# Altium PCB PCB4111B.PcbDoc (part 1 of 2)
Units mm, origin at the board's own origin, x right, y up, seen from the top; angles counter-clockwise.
Board outline 30 x 47 mm, 4 copper layers (Top Layer, Signal Layer 2, Signal Layer 3, Bottom Layer), stack 1.556 mm thick; 81 components, 93 nets, 294 pads, 415 vias.
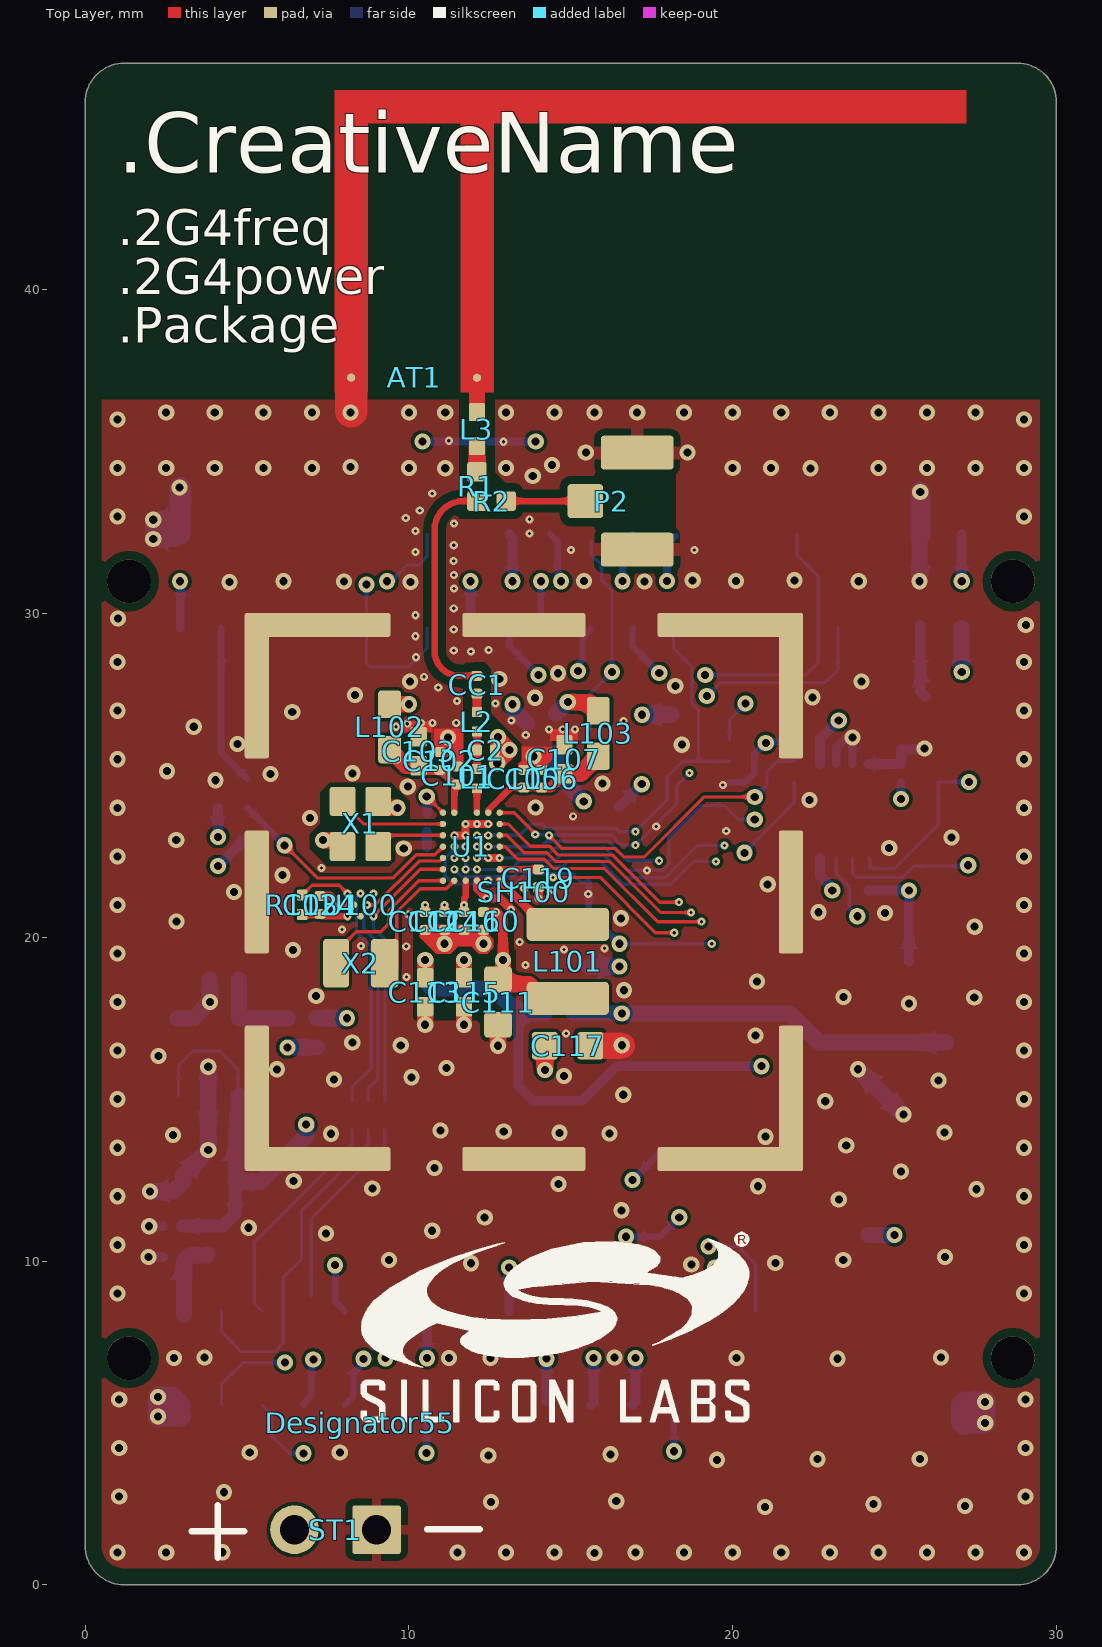
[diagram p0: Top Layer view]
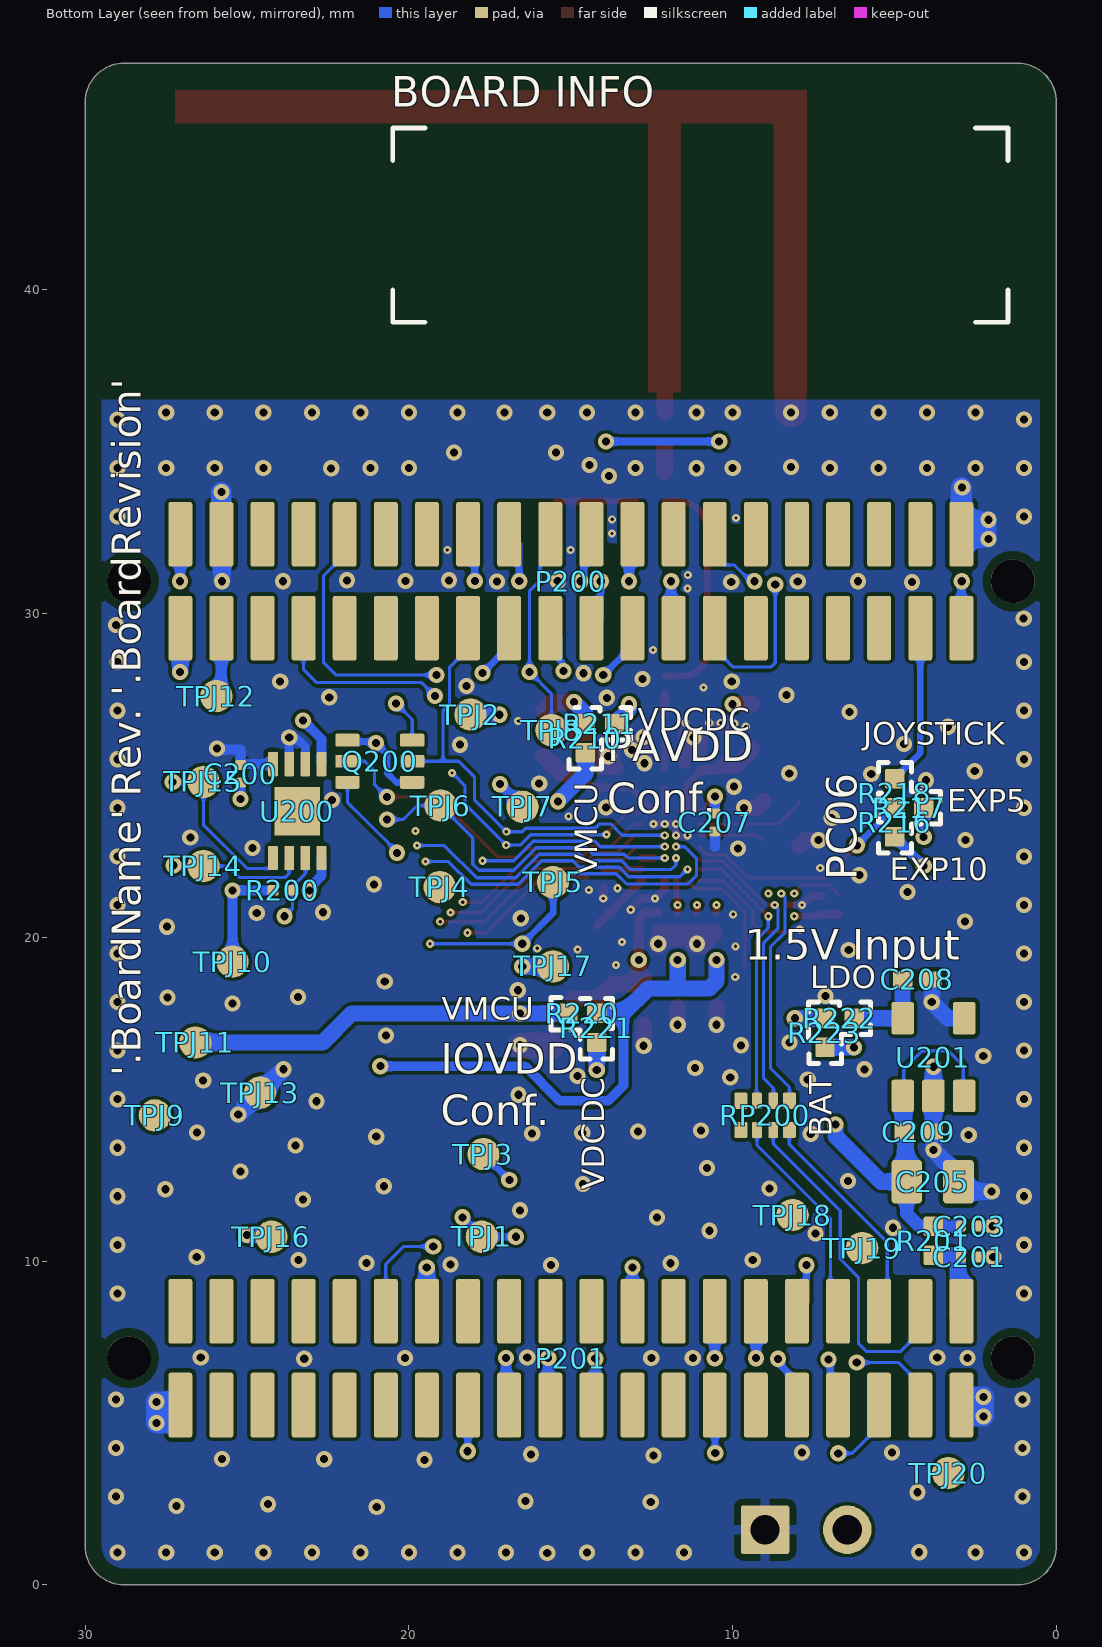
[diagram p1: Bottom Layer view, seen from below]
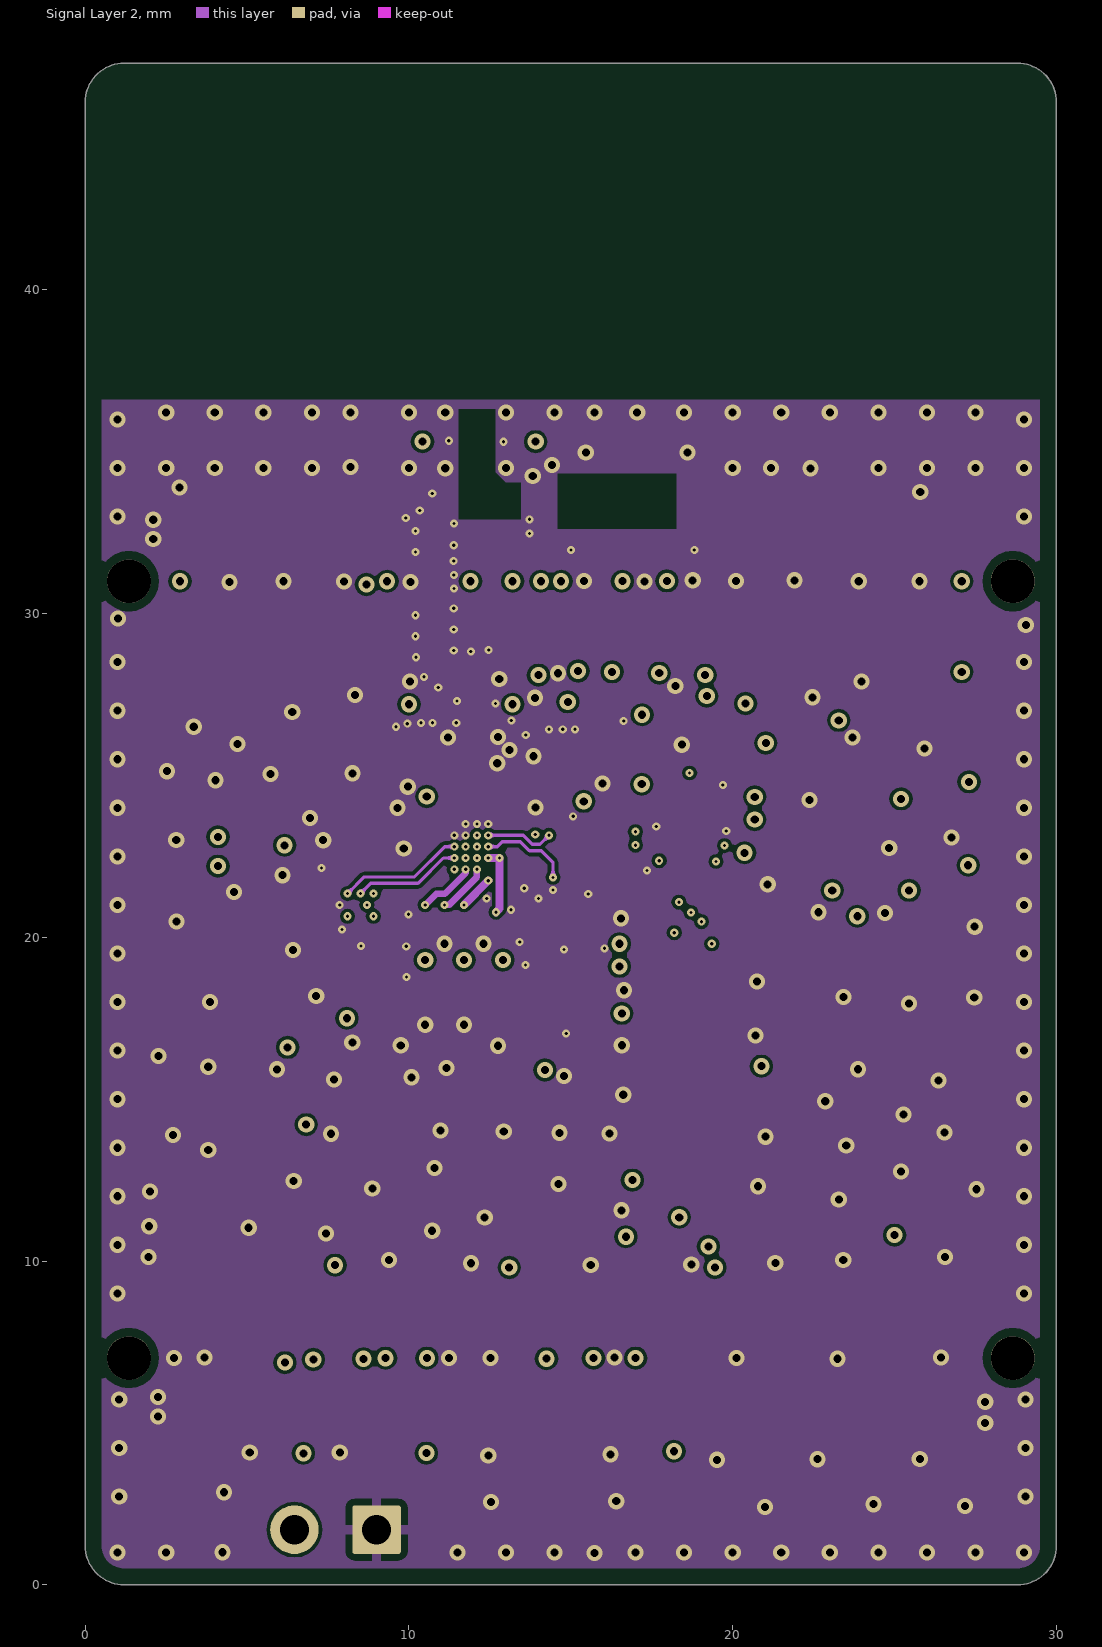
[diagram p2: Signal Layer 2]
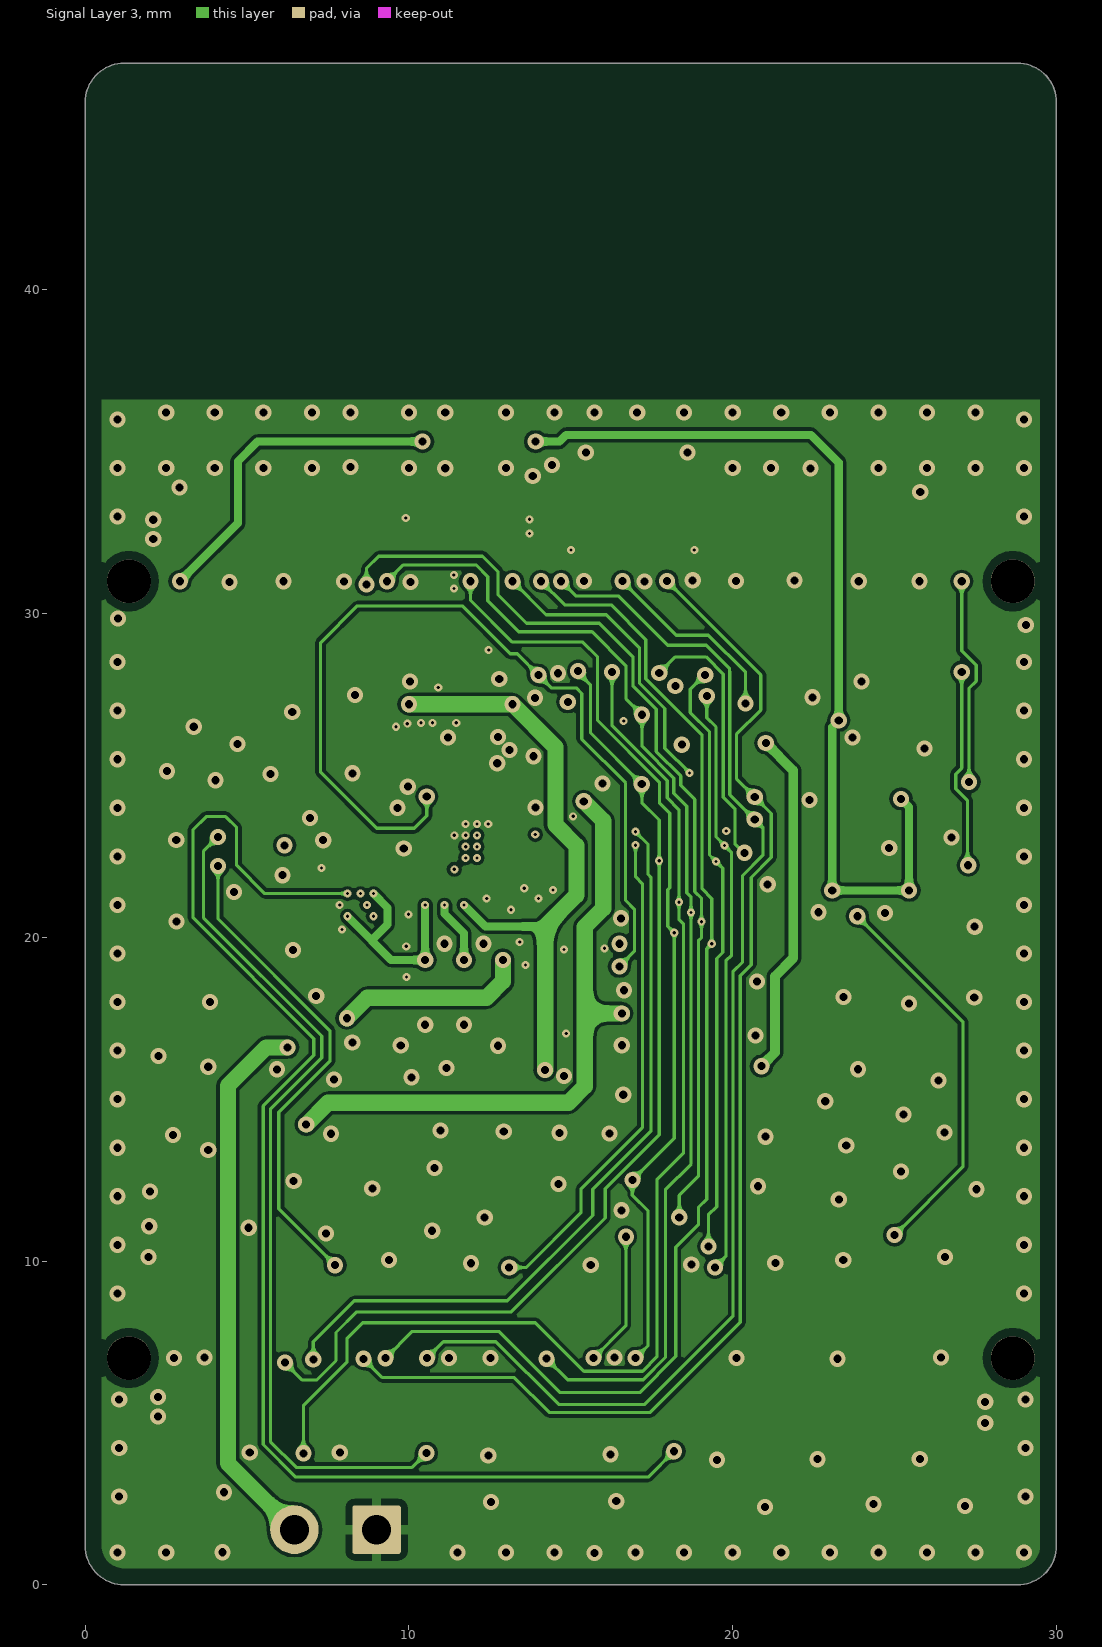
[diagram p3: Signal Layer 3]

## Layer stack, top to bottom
Top Solder: solder mask 0.0102, Solder Resist, Dk 3.5
Top Layer: signal copper 0.035
Dielectric 1: core 0.1, FR-4, Dk 4.2
Signal Layer 2: signal copper 0.018
Dielectric 3: prepreg 1.25, Dk 4.2
Signal Layer 3: signal copper 0.018
Dielectric 2: core 0.1, Dk 4.2
Bottom Layer: signal copper 0.035
Bottom Solder: solder mask 0.0102, Solder Resist, Dk 3.5

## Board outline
0,1.2 ccw(c1.2,1.2) 1.2,0 28.8,0 ccw(c28.8,1.2) 30,1.2 30,45.8 ccw(c28.8,45.8) 28.8,47 1.2,47 ccw(c1.2,45.8) 0,45.8

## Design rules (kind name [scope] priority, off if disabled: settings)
AcuteAngle [All] p1: minimum=7.00000000000000E+0001 checktracksonly=FALSE
BoardOutlineClearance [All] p1: gap=0.5 ignorepadtopadclearanceinfootprint=FALSE
Clearance Clearance_50Ohm [InNet('50R*') vs InNet('GND')] p1: gap=0.254 ignorepadtopadclearanceinfootprint=FALSE except(0: Arc-Hole Track-Hole SMDPad-Hole THPad-Hole Via-Hole Fill-Hole Poly-Hole Region-Hole Text-Hole)
Clearance Clearance_to_Holes [InPadClass('NPTH')] p2: gap=0.254 ignorepadtopadclearanceinfootprint=FALSE except(0: Arc-Hole Track-Hole SMDPad-Hole THPad-Hole Via-Hole Fill-Hole Poly-Hole Region-Hole Text-Hole)
Clearance Clerance_Polygon [InPolygon] p3: gap=0.1 ignorepadtopadclearanceinfootprint=FALSE except(0: Arc-Hole Track-Hole SMDPad-Hole THPad-Hole Via-Hole Fill-Hole Poly-Hole Region-Hole Text-Hole)
Clearance Clearance_General [All] p4: gap=0.1 ignorepadtopadclearanceinfootprint=FALSE except(0: Arc-Hole Track-Hole SMDPad-Hole THPad-Hole Via-Hole Fill-Hole Poly-Hole Region-Hole Text-Hole)
HoleToHoleClearance HoleToHoleClearance_ANT1toPAD [Incomponent ('ANT1') vs ISpad] p1: gap=0 allowstackedmicrovias=TRUE
HoleToHoleClearance HoleToHoleClearance_R1toR2_1 [Incomponent ('R1') vs Incomponent ('R2')] p2: gap=0 allowstackedmicrovias=TRUE
HoleToHoleClearance HoleToHoleClearance_U1toVIA_1 [InComponent ('U1') vs IsVia] p3: gap=0 allowstackedmicrovias=TRUE
HoleToHoleClearance [All] p4: gap=0.245 allowstackedmicrovias=TRUE
MinimumSolderMaskSliver [All] p1: minsoldermaskwidth=0.075
PolygonConnect PolygonConnect_TH [InComponent('ST1') or InComponent('P2')] p1: thpad.connectstyle=Relief thpad.reliefconductorwidth=0.3 thpad.reliefentries=4 thpad.polygonreliefangle="90 Angle" thpad.airgapwidth=0.2 smdpad.connectstyle=Relief smdpad.reliefconductorwidth=0.4 smdpad.reliefentries=4 smdpad.polygonreliefangle="90 Angle" smdpad.airgapwidth=0.2 via.connectstyle=Relief via.reliefconductorwidth=0.254 via.reliefentries=4 via.polygonreliefangle="90 Angle" via.airgapwidth=0.254
PolygonConnect Polygon_VIA_Connect [IsVia] p2: connectstyle=Direct reliefconductorwidth=0.254 reliefentries=4 polygonreliefangle="90 Angle" airgapwidth=0.254
PolygonConnect PolygonConnect_SH100 [InComponent('SH100')] p3: connectstyle=Direct reliefconductorwidth=0.254 reliefentries=4 polygonreliefangle="90 Angle" airgapwidth=0.127
PolygonConnect [All] p4: connectstyle=NoConnect reliefconductorwidth=0.254 reliefentries=4 polygonreliefangle="90 Angle" airgapwidth=0.127
RoutingVias [All] p1: holewidth=0.3 width=0.65 viastyle="Through Hole" minholewidth=0.25 minwidth=0.5 maxholewidth=1 maxwidth=1.5
ShortCircuit ShortCircuit_ANTtoPAD [InNet('NetAT1_1') vs InNet('GND')] p1: allowed=TRUE
ShortCircuit ShortCircuit_R1toR2_1 [Incomponent ('R1') vs Incomponent ('R2')] p2: allowed=TRUE
ShortCircuit [All] p3: allowed=FALSE
SilkToSilkClearance [All] p1: silktosilkclearance=0.102
SilkToSolderMaskClearance [IsPad] p1: minsilkscreentomaskgap=0.102 clearancetoexposedcopper=TRUE
SolderMaskExpansion [All] p1: expansion=0.051 istentingtop=FALSE
Width 50ohm [InNet('50R*')] p1: maxlimit=0.55 minlimit=0.2 preferedwidth=0.2
Width [All] p2: maxlimit=5.08 minlimit=0.1 preferedwidth=0.125
25 further rules are at their usual default settings.

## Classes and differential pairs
pad class NPTH: P200-M1 P200-M2 P201-M1 P201-M2

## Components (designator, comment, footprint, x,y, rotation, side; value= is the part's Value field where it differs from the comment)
AT1 "INVERTED_F" EM358x_INVERTED_F 7.714,36.835 r0 top net-tie
C2 "1P3" C0201_L 12.375,25.78 r0 top
C101 "120P" C0201_L 11.5,25 r90 top
C102 "100N" C0201_L 10.95,25.45 r90 top
C103 "1U" C0402_L#1 10.3,25.75 r90 top
C105 "120P" C0201_L 13.55,24.9 r90 top
C106 "100N" C0201_L 14.1,24.9 r90 top
C107 "1U" C0402_L#1 14.8,25.5 r90 top
C110 "100N" C0201_L 12.3,20.5 r270 top
C111 "10U" C0603_L 12.75,18 r270 top
C112 "10N" C0201_L 10.5,20.5 r270 top
C113 "1U" C0402_L#1 10.5,18.3 r270 top
C114 "100N" C0201_L 11.1,20.5 r270 top
C115 "1U" C0402_L#2 11.7,18.3 r270 top
C116 "100N" C0201_L 11.7,20.5 r270 top
C117 "4U7" C0603_L 14.9,16.65 r0 top
C119 "1U" C0201_L 14,21.825 r270 top
C124 "100N" C0201_L 7.25,21 r90 top
C200 "100N" C0201_L 25.2,25.05 r90 bottom
C201 "100N" C0201_L 2.675,10.125 r180 bottom
C203 "100N" C0201_L 2.675,11.075 r180 bottom
C205 "10U" C0805_L 3.825,12.45 r180 bottom
C207 "100N" C0201_L 10.55,23.55 r270 bottom
C208 "1U" C0402_L#1 4.3,18.7 r180 bottom
C209 "1U" C0402_L#1 4.25,14 r180 bottom
CC1 "18P" C0201_L 12.1,27.8 r90 top
Designator39 "Comment" PCB_SPEC_4_LAYER -68.7,110.2 r0 top
Designator55 "Comment" LOGO_SILABS_W12.0 8.5,5 r0 top
L1 "3N5" COIL_0201_L 12.1,24.9 r90 top
L2 "3N8" COIL_0201_L 12.1,26.66 r90 top
L3 "0R" COIL_0402_L 12.1,35.7 r90 top
L101 "2U2" COIL_1008_L 14.908,19.257 r270 top
L102 "BLM18AG102SN1" COIL_MUR_BLM18_0603 9.4,26.5 r270 top
L103 "BLM18AG102SN1" COIL_MUR_BLM18_0603 15.85,26.3 r270 top
P2 "U.FL" COAX_HIROSE_U.FL_CL331-0471 17.05,33.475 r90 top
P200 "SOCKET_WCON_2X20_1.27MM_SMD" SAM_SFC-120-T2-D-A-2X20_SNUM 15,31 r0 bottom locked
P201 "SOCKET_WCON_2X20_1.27MM_SMD" SAM_SFC-120-T2-D-A-2X20_SNUM 15,7 r0 bottom locked
Q200 "BSS84" SOT-363 20.903,25.439 r0 bottom
R1 "0R" R0402_L 12.1,33.925 r90 top
R2 "0R" R0402_L 12.55,33.475 r0 top
R103 "330K" R0201_L 6.7,21 r270 top
R200 "10K" R0201_L 23.9,21.45 r0 bottom
R201 "0R" R0402_L 3.8,10.625 r90 bottom
R210 "0R" R0402_L 14.55,26.15 r270 bottom
R211 "0R" R0402_L 14.1,26.6 r0 bottom
R216 "0R" R0402_L 5.001,23.55 r270 bottom
R217 "0R" R0402_L 4.55,24 r180 bottom
R218 "0R" R0402_L 5,24.45 r90 bottom
R220 "0R" R0402_L 14.65,17.65 r0 bottom
R221 "0R" R0402_L 14.2,17.2 r90 bottom
R222 "0R" R0402_L 6.7,17.5 r0 bottom
R223 "0R" R0402_L 7.15,17.05 r90 bottom
RP200 "100R" RES_MNR04-8 9,14.5 r0 bottom
SH100 "RF_SHIELD_FRAME_BMI-S-202-F" LAIRD_BMI-S-202-F 13.55,21.4 r90 top locked
ST1 "2X1 2.54MM" HEADER2X1_2.54MM_TH 9,1.7 r180 top
TPJ1 "TPJ_SMD" TP_1.0_SMD 17.75,10.75 r90 bottom locked
TPJ2 "TPJ_SMD" TP_1.0_SMD 18.1,26.88 r90 bottom locked
TPJ3 "TPJ_SMD" TP_1.0_SMD 17.7,13.3 r90 bottom locked
TPJ4 "TPJ_SMD" TP_1.0_SMD 19.05,21.55 r90 bottom locked
TPJ5 "TPJ_SMD" TP_1.0_SMD 15.55,21.7 r90 bottom locked
TPJ6 "TPJ_SMD" TP_1.0_SMD 19.02,24.07 r90 bottom locked
TPJ7 "TPJ_SMD" TP_1.0_SMD 16.49,24.03 r90 bottom locked
TPJ8 "TPJ_SMD" TP_1.0_SMD 15.6,26.4 r90 bottom locked
TPJ9 "TPJ_SMD" TP_1.0_SMD 27.85,14.5 r90 bottom locked
TPJ10 "TPJ_SMD" TP_1.0_SMD 25.45,19.25 r90 bottom locked
TPJ11 "TPJ_SMD" TP_1.0_SMD 26.6,16.75 r90 bottom locked
TPJ12 "TPJ_SMD" TP_1.0_SMD 25.95,27.45 r90 bottom locked
TPJ13 "TPJ_SMD" TP_1.0_SMD 24.6,15.2 r90 bottom locked
TPJ14 "TPJ_SMD" TP_1.0_SMD 26.35,22.2 r90 bottom locked
TPJ15 "TPJ_SMD" TP_1.0_SMD 26.35,24.8 r90 bottom locked
TPJ16 "TPJ_SMD" TP_1.0_SMD 24.25,10.75 r90 bottom locked
TPJ17 "TPJ_SMD" TP_1.0_SMD 15.55,19.1 r90 bottom locked
TPJ18 "TPJ_SMD" TP_1.0_SMD 8.15,11.42 r90 bottom locked
TPJ19 "TPJ_SMD" TP_1.0_SMD 6,10.4 r90 bottom locked
TPJ20 "TPJ_SMD" TP_1.0_SMD 3.34,3.45 r90 bottom locked
U1 "EFR32BG27C320F768GJ39-A" WLCSP39 11.925,22.8 r180 top
U100 "MX25R8035F" BGA8_M040_1.24X1.75_WLCSP 8.5,21 r90 top
U200 "24AA024" TDFN8_M050_2.0X3.0_EP 23.45,23.9 r270 bottom
U201 "TPS7A03" SOT-23-5 3.8,16.3 r90 bottom
X1 "38.4MHz" KDS_DSX211SH_2016 8.5,23.5 r90 top
X2 "32.768 kHz" X_MCS_CM8V-T1A 8.5,19.2 r0 top

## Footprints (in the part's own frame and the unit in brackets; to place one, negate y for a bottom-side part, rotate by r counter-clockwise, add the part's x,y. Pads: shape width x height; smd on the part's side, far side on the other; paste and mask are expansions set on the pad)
BGA8_M040_1.24X1.75_WLCSP [mm] "BGA, 8 pin. U100"
  round 0.21 smd mask+0.038: A1(-0.35,0.4) A3(0.35,0.4) B2(0,0.2) C1(-0.35,0) C3(0.35,0) D2(0,-0.2) E1(-0.35,-0.4) E3(0.35,-0.4)
  body extent -0.63,-0.89 0.63,0.88, height 0.52
C0201_L [mm] "Capacitor, Chip; 0.60 mm L X 0.30 mm W X 0.33 mm H body"
  rrect52% 0.31x0.34 smd: 1(-0.275,0) 2(0.275,0)
  body extent -0.3,-0.15 0.3,0.15, height 0.3
C0402_L#1 [mm] "Chip Capacitor, 2-Leads, Body 1.0x0.5mm, IPC High Density"
  rrect20% 0.6x0.5 smd mask+0.051: 1(-0.45,0) 2(0.45,0)
  body extent -0.5,-0.25 0.5,0.25, height 0.6
C0402_L#2 [mm] "Chip Capacitor, 2-Leads, Body 1.0x0.5mm, IPC High Density"
  rrect20% 0.6x0.5 smd mask+0.051: 1(-0.455,0) 2(0.45,0)
  body extent -0.5,-0.25 0.5,0.25, height 0.6
C0603_L [mm] "Capacitor, 0603, High Density (C)"
  rrect25% 0.8x0.85 smd: 1(-0.7,0) 2(0.7,0)
  body extent -0.8,-0.4 0.8,0.4, height 0.95
C0805_L [mm] "Capacitor, 0805"
  rrect25% 0.95x1.35 smd: 1(-0.8,0) 2(0.8,0)
  body extent -1.1,-0.72 1.1,0.72, height 1.45
COAX_HIROSE_U.FL_CL331-0471 [mm] "COAX_HIROSE_U.FL_CL331-0471"
  rrect20% 1.05x1.1 smd mask+0.051: 1(0,1.6)
  rrect20% 1.05x2.25 smd mask+0.051: 2(-1.5,0) 3(1.5,0)
  Top Layer pour cut-out: -0.85,0.9 0.85,0.9 0.85,0.9 0.85,-1.2 -0.85,-1.2 -0.85,-1.2
  body extent -1.3,-1.55 1.3,1.3, height 0.9
COIL_0201_L [mm] "JELF243C-0021"
  rrect10% 0.3x0.3 smd: 1(-0.3,0) 2(0.3,0)
  body extent -0.32,-0.17 0.32,0.17, height 0.33
COIL_0402_L [mm] "COIL_0402_L"
  rrect20% 0.55x0.5 smd mask+0.051: 1(-0.525,0) 2(0.525,0)
  body extent -0.5,-0.25 0.5,0.25, height 0.5
COIL_1008_L [mil] "Chip Inductors, 1008 (2520), Coilcraft (190207)"
  rrect25% 40x100 smd: 1(-45,0) 2(45,0)
  body extent -58,-55 57,55, height 80
COIL_MUR_BLM18_0603 [mm] "COIL_MUR_BLM18P_0603"
  rrect25% 0.85x0.7 smd mask+0.051: 1(-0.7,0) 2(0.7,0)
  body extent -0.88,-0.48 0.87,0.48, height 0.95
EM358x_INVERTED_F [mil] "F-ANTENNA INVERSE 19.5 mm"
  round 10 smd paste-10 mask-10: 1(172.68,17.72) 2(19.68,17.85)
  Top Layer region: 0,367.2 767.72,367.2 767.72,327.07 193,327.07 193,0 153,0 153,327.07 40,327.07 40,0 20,0 0,0
HEADER2X1_2.54MM_TH [mm] "Connector; Header; 2 Position"
  rrect10% 1.5x1.5 hole 0.9: 1(0,0)
  round 1.5 hole 0.9: 2(2.54,0)
  body extent -1.27,-1.27 3.68,1.27, height 9.7
KDS_DSX211SH_2016 [mm] "Copy of Silabs CE  X_KDS_DSX211SH_2.0X1.65-4"
  rrect20% 0.9x0.8 smd mask+0.051: 1(-0.7,-0.55) 2(0.7,-0.55) 3(0.7,0.55) 4(-0.7,0.55)
  body extent -1.07,-0.87 1.08,0.88, height 0.5
LAIRD_BMI-S-202-F [mm] "laired BMI-S-202-F"
  rrect20% 0.75x4.5 smd paste+0 mask+0.05: 1(-8.25,-6.375) 1(-8.25,6.375) 1(8.25,-6.375) 1(8.25,6.375)
  rrect20% 0.75x3.8 smd paste+0 mask+0.05: 1(-8.25,0) 1(8.25,0)
  rrect20% 4.5x0.75 smd paste+0 mask+0.05: 1(-6.375,8.25) 1(-6.375,-8.25) 1(6.375,8.25) 1(6.375,-8.25)
  rrect20% 3.8x0.75 smd paste+0 mask+0.05: 1(0,8.25) 1(0,-8.25)
  body extent -8.6,-8.6 8.6,8.6, height 5.5
LOGO_SILABS_W12.0 [mm] "LOGO_SILABS_W12.0 (170217)"
  silkscreen extent 0.03,0.03 11.99,5.88
PCB_SPEC_4_LAYER [mm]
R0201_L [mm] "Resistor (Chip2PinSM127P600-8N) (170921)"
  rrect25% 0.34x0.32 smd: 1(-0.3,0) 2(0.3,0)
  body extent -0.32,-0.13 0.32,0.13, height 0.3
R0402_L [mm] "Chip Resistor, 2-Leads, Body 1.0x0.5mm, IPC High Density"
  rrect20% 0.6x0.6 smd mask+0.051: 1(-0.45,0) 2(0.45,0)
  body extent -0.5,-0.25 0.5,0.25, height 0.6
RES_MNR04-8 [mm] "Chip resistor network 8pin"
  rrect20% 0.4x0.5 smd mask+0.051: 1(-0.75,-0.45) 4(0.75,-0.45) 5(0.75,0.45) 8(-0.75,0.45)
  rrect20% 0.3x0.5 smd mask+0.051: 2(-0.25,-0.45) 3(0.25,-0.45) 6(0.25,0.45) 7(-0.25,0.45)
  body extent -1,-0.4 1,0.4, height 0.5
SAM_SFC-120-T2-D-A-2X20_SNUM [mm]
  rrect20% 0.74x2 smd mask+0.05: 1(-12.065,1.45) 2(-12.065,-1.45) 3(-10.795,1.45) 4(-10.795,-1.45) 5(-9.525,1.45) 6(-9.525,-1.45) 7(-8.255,1.45) 8(-8.255,-1.45) 9(-6.985,1.45) 10(-6.985,-1.45) 11(-5.715,1.45) 12(-5.715,-1.45) 13(-4.445,1.45) 14(-4.445,-1.45) 15(-3.175,1.45) 16(-3.175,-1.45) 17(-1.905,1.45) 18(-1.905,-1.45) 19(-0.635,1.45) 20(-0.635,-1.45) 21(0.635,1.45) 22(0.635,-1.45) 23(1.905,1.45) 24(1.905,-1.45) 25(3.175,1.45) 26(3.175,-1.45) 27(4.445,1.45) 28(4.445,-1.45) 29(5.715,1.45) 30(5.715,-1.45) 31(6.985,1.45) 32(6.985,-1.45) 33(8.255,1.45) 34(8.255,-1.45) 35(9.525,1.45) 36(9.525,-1.45) 37(10.795,1.45) 38(10.795,-1.45) 39(12.065,1.45) 40(12.065,-1.45)
  round 1.35 hole 1.35 unplated paste-5.563 mask-5.563: M1(13.652,0) M2(-13.652,0)
  body extent -14.65,-1.58 14.65,2.25, height 4.57
SOT-23-5 [mm] "mic2776  3-Leads, Body 2.8x2.9mm, Pitch 0.95mm, IPC High Density"
  rrect20% 1x0.7 smd: 1(-1.2,0.95) 2(-1.2,0) 3(-1.2,-0.95) 4(1.2,-0.95) 5(1.2,0.95)
  body extent -1.4,-1.5 1.4,1.5, height 1.1
SOT-363 [mm] "SOT363 IPC L"
  rrect25% 0.75x0.4 smd: 1(-1,0.65) 2(-1,0) 3(-1,-0.65) 4(1,-0.65) 5(1,0) 6(1,0.65)
  body extent -1.15,-1.05 1.15,1.05, height 1
TDFN8_M050_2.0X3.0_EP [mm] "TDFN8_M050_2.0x3.0_EP"
  rrect20% 0.75x0.3 smd mask+0.051: 1(-1.45,0.75) 2(-1.45,0.25) 3(-1.45,-0.25) 4(-1.45,-0.75) 5(1.45,-0.75) 6(1.45,-0.25) 7(1.45,0.25) 8(1.45,0.75)
  rect 1.5x1.4 smd mask+0.051: 9(0,0)
  body extent -1.5,-1 1.5,1, height 1.01
TP_1.0_SMD [mm] "Test Point, 1.0 mm, SMD"
  round 1 smd paste-0.501: 1(0,0)
  body extent -0.2,-0.2 0.2,0.2, height 0.01
WLCSP39 [mm]
  round 0.2 smd mask+0.04: A1(-0.875,1.05) A2(-0.525,1.05) A3(-0.175,1.05) A4(0.175,1.05) A5(0.525,1.05) A6(0.875,1.05) B1(-0.875,0.7) B3(-0.175,0.7) B4(0.175,0.7) B5(0.525,0.7) B6(0.875,0.7) C1(-0.875,0.35) C2(-0.525,0.35) C3(-0.175,0.35) C4(0.175,0.35) C5(0.525,0.35) C6(0.875,0.35) D1(-0.875,0) D2(-0.525,0) D3(-0.175,0) D4(0.175,0) D5(0.525,0) D6(0.875,0) E1(-0.875,-0.35) E2(-0.525,-0.35) E3(-0.175,-0.35) E4(0.175,-0.35) E5(0.525,-0.35) E6(0.875,-0.35) F1(-0.875,-0.7) F2(-0.525,-0.7) F3(-0.175,-0.7) F4(0.175,-0.7) F6(0.875,-0.7) G1(-0.875,-1.05) G2(-0.525,-1.05) G3(-0.175,-1.05) G5(0.525,-1.05) G6(0.875,-1.05)
  body extent -1.16,-1.33 1.16,1.33, height 0.51
X_MCS_CM8V-T1A [mm] "Crystal MCS CM8V-T1A (2 pin)"
  rrect25% 0.8x1.5 smd mask+0.051: 1(-0.75,0)
  rrect25% 0.85x1.5 smd mask+0.051: 2(0.75,0)
  body extent -1,-0.6 1,0.6, height 0.95

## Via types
v1: diameter 0.5, hole 0.25, Top Layer to Bottom Layer, tented both sides, 309 vias
v2: diameter 0.25, hole 0.1, Top Layer to Bottom Layer, tented both sides, 63 vias
v3: diameter 0.25, hole 0.1, Top Layer to Signal Layer 2, tented top, 39 vias
v4: diameter 0.25, hole 0.1, Top Layer to Bottom Layer, tented top, 2 vias
v5: diameter 0.25, hole 0.1, Top Layer to Signal Layer 2, tented both sides, 2 vias

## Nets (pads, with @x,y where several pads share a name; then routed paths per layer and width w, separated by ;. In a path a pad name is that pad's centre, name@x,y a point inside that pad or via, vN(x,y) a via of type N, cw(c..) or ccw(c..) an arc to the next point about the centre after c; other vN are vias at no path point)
1V5: C110.1 C111.1 L101.2 R222.2 R223.2 U1.C1 U1.C2 | length 14.3
  Top Layer w0.25: v5(12.45,22.45) v5(12.8,22.45)
  Top Layer w0.3: C110.1@12.315,20.775 v3(12.688,20.775) 12.9,20.563 v1(12.9,19.3)
  Top Layer w0.5: v1(12.9,19.3) 12.9,18.85 C111.1@12.75,18.7 12.9,18.55 13.71,18.55 14.146,18.114 L101.2@14.908,18.114
  Signal Layer 2 w0.25: v5(12.45,22.45) v5(12.8,22.45) 12.8,20.887 v3(12.688,20.775)
  Signal Layer 3 w0.5: v1(8.081,17.5) 8.713,18.132 12.395,18.132 12.9,18.637 v1(12.9,19.3)
  Bottom Layer w0.5: R222.2@7.15,17.5 v1(8.081,17.5)
3V3: C200.1 P200.1 R200.2 TPJ10.1 U200.1 U200.8 | length 50.9
  Signal Layer 3 w0.254: v1(2.925,31) 4.717,32.791 4.717,34.705 5.324,35.313 v1(10.418,35.313) ; v1(13.913,35.313) 14.648,35.313 14.856,35.521 22.42,35.521 23.275,34.666 v1(23.275,26.7) 23.075,26.5 v1@23.075,21.5 ; v1(23.075,21.45) v1@23.075,21.5 ; v1(25.2,24.275) 25.45,24.025 v1(25.45,21.45) 22.975,21.45 23.05,21.525 v1@23.075,21.5
  Bottom Layer w0.254: v1(2.925,31) 2.95,31 2.975,30.975 2.935,30.935 P200.1@2.935,29.55 ; v1(10.418,35.313) v1(13.913,35.313) ; v1(25.2,24.275) C200.1@25.2,24.775
  Bottom Layer w0.305: U200.8@22.7,22.45 22.7,21.9 23.075,21.525 v1(23.075,21.45) ; U200.1@22.7,25.35 22.7,26.125 v1(23.275,26.7) ; R200.2@24.2,21.45 25.35,21.45 25.45,21.35 v1(25.45,21.45) TPJ10.1@25.45,19.25
5V: P200.37 TPJ12.1 | length 2.2
  Bottom Layer w0.33: P200.37@25.795,29.635 P200.37@25.795,29.55 25.795,27.605 TPJ12.1@25.95,27.45
50R_IFA: AT1.1 L3.2 | length 1.1
  Top Layer w0.5: L3.2@12.1,36.225 AT1.1@12.1,37.285
50R_L3: L3.1 R1.2 | length 0.8
  Top Layer w0.5: R1.2@12.1,34.375 L3.1@12.1,35.175
50R_P2: P2.1 R2.2 | length 2.5
  Top Layer w0.2: R2.2@13,33.475 P2.1@15.45,33.475
50R_R1: CC1.2 R1.1 R2.1 | length 7.3
  Top Layer w0.2: CC1.2@12.1,28.075 11.55,28.075 cw(c11.55,28.834) 10.792,28.834 10.792,32.589 cw(c11.677,32.589) 11.677,33.475 R1.1@12.1,33.475
BOARD_ID_SCL: P200.39 TPJ14.1 U200.6 | length 12.1
  Signal Layer 3 w0.1: v1(27.075,28.2) 27.075,25.228 26.889,25.042 26.889,24.588 27.25,24.227 27.25,22.275 27.2,22.225 v1(27.275,22.225)
  Bottom Layer w0.1: U200.6@23.7,22.45 23.7,21.975 23.825,21.85 25.25,21.85 25.6,22.2 TPJ14.1@26.35,22.2 27.375,22.2 27.35,22.225 v1(27.275,22.225)
  Bottom Layer w0.5: P200.39@27.065,29.55 27.065,28.21 v1(27.075,28.2)
BOARD_ID_SDA: P200.40 TPJ15.1 U200.5 | length 13.3
  Signal Layer 3 w0.102: v1(27.075,31) 27.075,28.856 27.526,28.405 27.526,27.917 27.3,27.691 v1(27.3,24.8)
  Bottom Layer w0.102: U200.5@24.2,22.45 24.25,22.4 24.25,22.125 25,22.125 26.35,23.475 TPJ15.1@26.35,24.8 v1(27.3,24.8) ; v1(27.075,31) v1@27.065,31 ; v1@27.065,31 27.065,30.965 27.03,31 v1@27.065,31
  Bottom Layer w0.3: v1@27.065,31 P200.40@27.065,32.45
BOARD_ID_WP: R200.1 TPJ16.1 U200.7 | length 15
  Signal Layer 3 w0.1: v1(23.85,20.65) 27.112,17.388 27.112,12.912 v1(25,10.8)
  Bottom Layer w0.1: U200.7@23.2,22.45 23.2,21.966 23.6,21.566 R200.1@23.6,21.45 23.6,20.9 v1(23.85,20.65) ; TPJ16.1@24.2,10.8 TPJ16.1@24.25,10.75
  Bottom Layer w0.5: TPJ16.1@24.2,10.8 v1(25,10.8)
EFR32_#RESET: C207.1 P200.17 TPJ17.1 U1.G6 | length 31.7
  Top Layer w0.1: v1(10.55,24.35) U1.G6@11.05,23.85
  Signal Layer 3 w0.1: v1(10.55,24.35) 10.55,23.75 10.167,23.367 9.001,23.367 7.268,25.1 7.268,29.101 8.405,30.238 11.646,30.238 13.126,28.757 13.343,28.757 v1(14,28.1) 14.397,27.703 15.166,27.703 15.337,27.532 15.337,26.123 16.692,24.768 16.692,21.137 16.964,20.865 16.964,19.564 v1(16.5,19.1)
  Bottom Layer w0.2: P200.17@13.095,29.55 13.095,29.005 v1(14,28.1)
  Bottom Layer w0.3: C207.1@10.55,23.825 v1(10.55,24.35)
  Bottom Layer w0.5: TPJ17.1@15.55,19.1 v1(16.5,19.1)
EFR32_PA00: P200.22 P201.5 TPJ8.1 U1.F1 | length 52.3
  Top Layer w0.1: U1.F1@12.8,23.5 13.064,23.5 13.75,22.814 14.345,22.814 14.618,22.541 16.289,22.541 17.744,21.086 v2(18.338,21.086)
  Signal Layer 3 w0.1: v1(6.739,4.059) 6.739,5.535 8.088,6.884 8.088,7.613 8.569,8.094 13.906,8.094 15.403,6.597 17.216,6.597 17.659,7.04 17.659,12.512 18.479,13.332 18.479,20.419 18.338,20.56 v2(18.338,21.086) 18.338,23.945 17.977,24.306 17.977,24.836 16.275,26.538 v1(16.275,28.2)
  Bottom Layer w0.1: P201.5@5.475,5.55 5.745,5.28 5.745,4.622 6.308,4.059 v1(6.739,4.059) ; TPJ8.1@15.6,26.4 15.6,27.525 v1(16.275,28.2) 16.275,30.7 15.95,31.025 15.95,31.5 15.629,31.822 P200.22@15.629,32.245
EFR32_PA01: P200.14 P201.19 TPJ2.1 U1.E1 | length 47.6
  Top Layer w0.1: U1.E1@12.8,23.15 13.024,23.15 13.56,22.614 14.262,22.614 14.535,22.341 16.197,22.341 17.772,20.765 v2(18.714,20.765)
  Signal Layer 3 w0.1: v1(9.325,31) 9.828,31.503 12.069,31.503 12.43,31.142 12.43,30.394 13.386,29.438 15.657,29.438 16.701,28.393 16.701,27.374 v1(17.2,26.875) 17.2,25.895 18.177,24.918 18.177,24.453 18.58,24.051 18.58,21.37 18.714,21.236 v2(18.714,20.765) 18.714,12.994 17.921,12.201 17.921,7.02 17.234,6.332 14.898,6.332 v1(14.247,6.984)
  Bottom Layer w0.1: v1@9.325,31.025 9.475,31.025 9.95,31.5 10.3,31.5 10.555,31.755 P200.14@10.555,32.45
  Bottom Layer w0.2: P201.19@14.247,5.668 P201.19@14.365,5.55
  Bottom Layer w0.3: P201.19@14.247,5.668 v1(14.247,6.984)
  Bottom Layer w0.5: v1(17.2,26.875) TPJ2.1@18.1,26.875
EFR32_PA02: P200.13 P201.21 TPJ1.1 U1.D1 | length 49.2
  Top Layer w0.1: U1.D1@12.8,22.8 12.979,22.8 13.366,22.414 14.179,22.414 14.468,22.125 16.038,22.125 17.68,20.483 v2(19.038,20.483)
  Signal Layer 3 w0.1: v1(8.686,30.9) 8.686,31.392 9.067,31.773 12.272,31.773 12.751,31.294 12.751,30.583 13.631,29.703 15.88,29.703 16.917,28.665 16.917,27.772 17.64,27.049 17.64,25.738 18.393,24.985 18.393,24.692 18.825,24.261 18.825,21.411 19.038,21.199 v2(19.038,20.483) 19.038,19.994 18.941,19.898 18.941,12.616 18.35,12.025 v1(18.35,11.35) ; v1@15.6,7 v1@15.625,7.025 ; v1(15.7,7) 16.7,8 v1(16.7,10.75)
  Bottom Layer w0.1: v1@8.686,31.007 v1(8.686,30.9) 8.686,28.484 8.824,28.346 9.981,28.346 10.555,28.921 P200.13@10.555,29.55
  Bottom Layer w0.2: v1(16.7,10.75) TPJ1.1@17.75,10.75 v1(18.35,11.35)
  Bottom Layer w0.3: P201.21@15.635,5.55 15.7,5.615 v1(15.7,7)
EFR32_PA03: P200.15 P201.23 TPJ3.1 U1.D2 | length 40.2
  Top Layer w0.1: v3(14.45,21.85) 15.906,21.85 17.614,20.142 v2(18.195,20.142)
  Signal Layer 2 w0.1: v3(12.45,22.8) 12.73,22.8 12.88,22.95 13.444,22.95 13.721,22.673 14.083,22.673 14.45,22.306 v3(14.45,21.85)
  Signal Layer 3 w0.1: v1(11.9,31) 11.9,30.415 13.194,29.121 15.367,29.121 15.823,28.666 15.823,26.707 17.736,24.794 17.736,24.154 18.057,23.833 18.057,21.53 17.993,21.466 17.993,20.344 v2(18.195,20.142) 18.195,13.795 v1(16.9,12.5) 16.9,12.033 17.383,11.55 17.383,7.383 v1(17,7)
  Bottom Layer w0.2: P201.23@16.9,5.555 P201.23@16.905,5.55 ; v1(16.9,12.5) TPJ3.1@17.7,13.3
  Bottom Layer w0.3: P200.15@11.825,29.55 11.9,29.625 v1(11.9,31) ; P201.23@16.905,5.55 17,5.645 v1(17,7)
EFR32_PA04: P200.21 P201.3 TPJ7.1 U1.D3 | length 42.6
  Signal Layer 2 w0.1: v2@12.095,22.8 v2(12.1,22.8)
  Signal Layer 3 w0.1: v1(6.168,6.862) 6.709,6.321 7.143,6.321 7.746,6.923 7.746,7.791 8.382,8.427 13.164,8.427 16.066,11.329 16.066,12.231 17.728,13.894 v2(17.728,22.365) 17.728,23.624 17.195,24.157 v1@17.195,24.725 ; v1(15.226,28.226) 15.226,28.174 15.609,27.791 15.609,26.311 v1(17.19,24.73)
  Bottom Layer w0.1: P201.3@4.205,5.55 4.205,6.193 4.874,6.862 v1(6.168,6.862) ; v2(12.1,22.8) 14.086,22.8 14.253,22.967 16.16,22.967 16.762,22.365 v2(17.728,22.365) ; P200.21@15.6,29.515 P200.21@15.635,29.55
  Bottom Layer w0.2: v1(15.226,28.226) 15.263,28.263 15.263,28.484 15.362,28.584 15.362,28.591 15.365,28.595 15.365,29.28 P200.21@15.6,29.515
  Bottom Layer w0.3: TPJ7.1@16.49,24.03 v1(17.19,24.73)
EFR32_PA05: P200.19 P201.12 TPJ5.1 U1.D4 | length 52.2
  Signal Layer 3 w0.102: v1(9.276,6.999) 10.102,7.825 12.777,7.825 14.666,5.936 17.125,5.936 18.243,7.054 18.243,10.421 18.942,11.12 18.942,11.653 19.2,11.911 19.2,19.647 v2(19.354,19.8) 19.354,21.197 19.054,21.496 19.054,26.247 17.318,27.983 17.318,29.196 16.247,30.268 14.807,30.268 v1(14.075,31)
  Bottom Layer w0.1: v1(16.5,19.8) v2(19.354,19.8)
  Bottom Layer w0.102: v2(11.75,22.8) 11.481,22.8 11.121,22.44 11.121,21.906 11.379,21.648 13.281,21.648 13.594,21.961 15.046,21.961 15.307,21.7 TPJ5.1@15.55,21.7
  Bottom Layer w0.2: v1(14.075,31) 14.075,29.84 P200.19@14.365,29.55 ; TPJ5.1@15.55,21.7 15.55,20.75 v1(16.5,19.8)
  Bottom Layer w0.3: v1(9.276,6.999) 9.276,8.441 P201.12@9.285,8.45
EFR32_PA06: P200.20 P201.14 TPJ6.1 U1.C3 | length 52.3
  Signal Layer 3 w0.1: v1(10.554,6.999) 11.064,7.509 12.682,7.509 14.621,5.571 17.286,5.571 20.008,8.293 20.008,18.935 20.303,19.231 20.303,21.906 20.934,22.537 20.934,23.383 v1(20.68,23.637) 19.908,24.41 19.908,28.214 19.905,28.217 19.905,28.302 19.187,29.021 17.989,29.021 16.465,30.545 15.155,30.545 v1(14.7,31)
  Bottom Layer w0.1: v2(12.1,22.45) 13.233,22.45 13.345,22.562 14.311,22.562 14.516,22.767 16.068,22.767 16.763,22.072 17.837,22.072 18.027,22.262 18.027,23.077 TPJ6.1@19.02,24.07 19.753,24.07 20.186,23.637 v1(20.68,23.637)
  Bottom Layer w0.2: P200.20@14.365,32.45 14.599,32.216 14.599,31.182 14.7,31.081 v1(14.7,31)
  Bottom Layer w0.3: v1(10.554,6.999) P201.14@10.555,8.45
EFR32_PB00: P200.18 P201.18 U1.G1 | length 34.8
  Top Layer w0.1: U1.G1@12.8,23.85 13.249,23.85 13.901,23.198 v2(13.901,23.173)
  Signal Layer 3 w0.1: v1(13.095,9.8) 13.62,9.8 15.31,11.49 15.31,12.222 17.211,14.123 17.211,21.659 16.999,21.872 v2(16.999,22.846) ; v1(13.2,31) 14.233,29.967 16.092,29.967 17.117,28.941 17.117,27.855 17.904,27.068 17.904,25.841 v2(18.668,25.077)
  Bottom Layer w0.1: v2(13.901,23.173) 13.907,23.167 16.243,23.167 16.562,22.849 16.995,22.849 v2(16.999,22.846) 18.272,24.12 18.272,24.68 v2(18.668,25.077)
  Bottom Layer w0.3: P201.18@13.095,8.45 v1(13.095,9.8) ; P200.18@13.095,32.45 13.2,32.345 v1(13.2,31)
EFR32_PB01: P200.26 P201.9 Q200.5 U1.E2 | length 53.4
  Top Layer w0.1: v3(14.325,23.15) 14.734,22.741 16.372,22.741 16.633,22.48 17.265,22.48 19.123,24.338 v1(20.68,24.338)
  Signal Layer 2 w0.1: v3(12.45,23.15) 13.527,23.15 13.804,22.873 14.048,22.873 v3(14.325,23.15)
  Signal Layer 3 w0.1: v1(8.599,6.979) 9.178,6.4 13.252,6.4 14.331,5.322 17.456,5.322 20.236,8.102 20.236,18.818 20.574,19.155 20.574,21.847 21.195,22.468 21.195,23.824 v1(20.68,24.338) 20.116,24.902 20.116,26.266 20.869,27.019 20.869,28.107 v1(17.967,31.009)
  Bottom Layer w0.1: P200.26@18.175,32.45 P200.26@18.237,32.388 ; v1@20.689,24.338 21.062,24.711 21.062,25.131 21.37,25.439 Q200.5@21.903,25.439
  Bottom Layer w0.2: P201.9@8.015,5.55 8.285,5.82 8.285,6.538 8.542,6.795 8.542,6.921 v1(8.599,6.979) ; v1(17.967,31.009) 17.967,32.119 P200.26@18.237,32.388
EFR32_PB02: P200.25 P201.7 Q200.2 U1.E3 | length 38.9
  Signal Layer 3 w0.1: v1(7.045,6.956) 7.045,7.512 8.305,8.772 13.039,8.772 15.674,11.407 15.674,12.218 17.478,14.022 17.478,21.846 17.383,21.941 17.383,22.873 v2(16.994,23.262)
  Bottom Layer w0.1: P201.7@6.745,5.55 P201.7@6.757,5.562 ; v2(12.1,23.15) 13.419,23.15 13.773,23.504 14.112,23.504 14.248,23.367 16.389,23.367 16.494,23.262 v2(16.994,23.262) 17.161,23.43 17.98,24.248 17.98,24.96 18.459,25.439 18.947,25.439 ; P200.25@18.175,29.55 18.175,28.919 18.746,28.348 18.746,27.213 18.947,27.013 18.947,25.439 ; Q200.2@19.903,25.439 18.947,25.439
  Bottom Layer w0.2: P201.7@6.757,5.562 6.737,5.582 6.988,5.833 6.988,6.899 v1(7.045,6.956)
EFR32_PC00: P200.33 P201.28 U1.C4 | length 34.9
  Signal Layer 3 w0.1: v1(19.45,9.8) 19.791,10.141 19.791,19.272 19.967,19.447 19.967,22.617 v2(19.75,22.833) 19.483,23.1 19.483,26.499 19.2,26.782 v1(19.2,27.45) ; v1(19.2,27.45) 19.225,27.475 v1@19.2,27.5 ; v1(19.2,27.45) v1@19.2,27.5 ; v1@19.2,27.5 19.125,27.575 19.126,27.576 19.2,27.502 v1@19.2,27.5
  Bottom Layer w0.1: v2(11.75,22.45) 11.75,22.243 11.9,22.094 13.159,22.094 13.428,22.362 14.515,22.362 14.72,22.567 15.98,22.567 16.706,21.841 17.912,21.841 18.904,22.833 v2(19.75,22.833) ; v1(19.2,27.45) 19.177,27.45 19.127,27.5 19.125,27.5 19.126,27.501 19.251,27.501 19.624,27.874 22.858,27.874 23.255,28.271 P200.33@23.255,29.55 ; P201.28@19.445,8.45 P201.28@19.445,8.993
  Bottom Layer w0.5: P201.28@19.445,8.993 19.45,8.998 v1(19.45,9.8)
EFR32_PC01: P200.32 P201.30 U1.B5 | length 38.4
  Signal Layer 3 w0.1: v1@19.138,28.113 18.692,27.667 18.692,26.942 19.283,26.35 19.283,22.543 v2(19.486,22.34) 19.69,22.137 19.69,19.531 19.504,19.346 19.504,11.68 19.25,11.426 v1(19.25,10.45)
  Bottom Layer w0.1: v2(11.4,22.1) 11.633,21.867 13.216,21.867 13.511,22.162 14.736,22.162 14.941,22.367 15.897,22.367 16.624,21.641 18.082,21.641 18.781,22.34 v2(19.486,22.34) ; v1@19.225,28.1 22.246,28.1 22.643,28.498 22.643,31.162 21.985,31.82 P200.32@21.985,32.45 ; v1(19.25,10.45) 20.161,10.45 20.715,9.896 P201.30@20.715,8.45
  other v1: 19.15,28.1
EFR32_PC02: RP200.3 U1.B6 U100.E1 | length 8.6
  Top Layer w0.1: v2(8.9,20.65) 10.35,22.1 U1.B6@11.05,22.1
  Bottom Layer w0.1: v2(8.9,20.65) 8.9,20.288 9.262,19.926 9.262,14.962 RP200.3@9.25,14.95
